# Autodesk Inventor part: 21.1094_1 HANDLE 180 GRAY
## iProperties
Created: 2007-03
Part Number: 21.1094_1 HANDLE 180 GRAY
Document SubType Name: Modeling
Designer: Andy Moles
Material: ABS Plastic
Density: 1.06 g/cm^3
Mass: 60.9279 g
Surface Area: 218.997 cm^2
Volume: 57.4792 cm^3
Author: Andy Moles
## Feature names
1. Extrusion1
2. Extrusion2
3. Extrusion3
4. Extrusion4
5. Fillet1
6. Fillet2
7. Fillet3
